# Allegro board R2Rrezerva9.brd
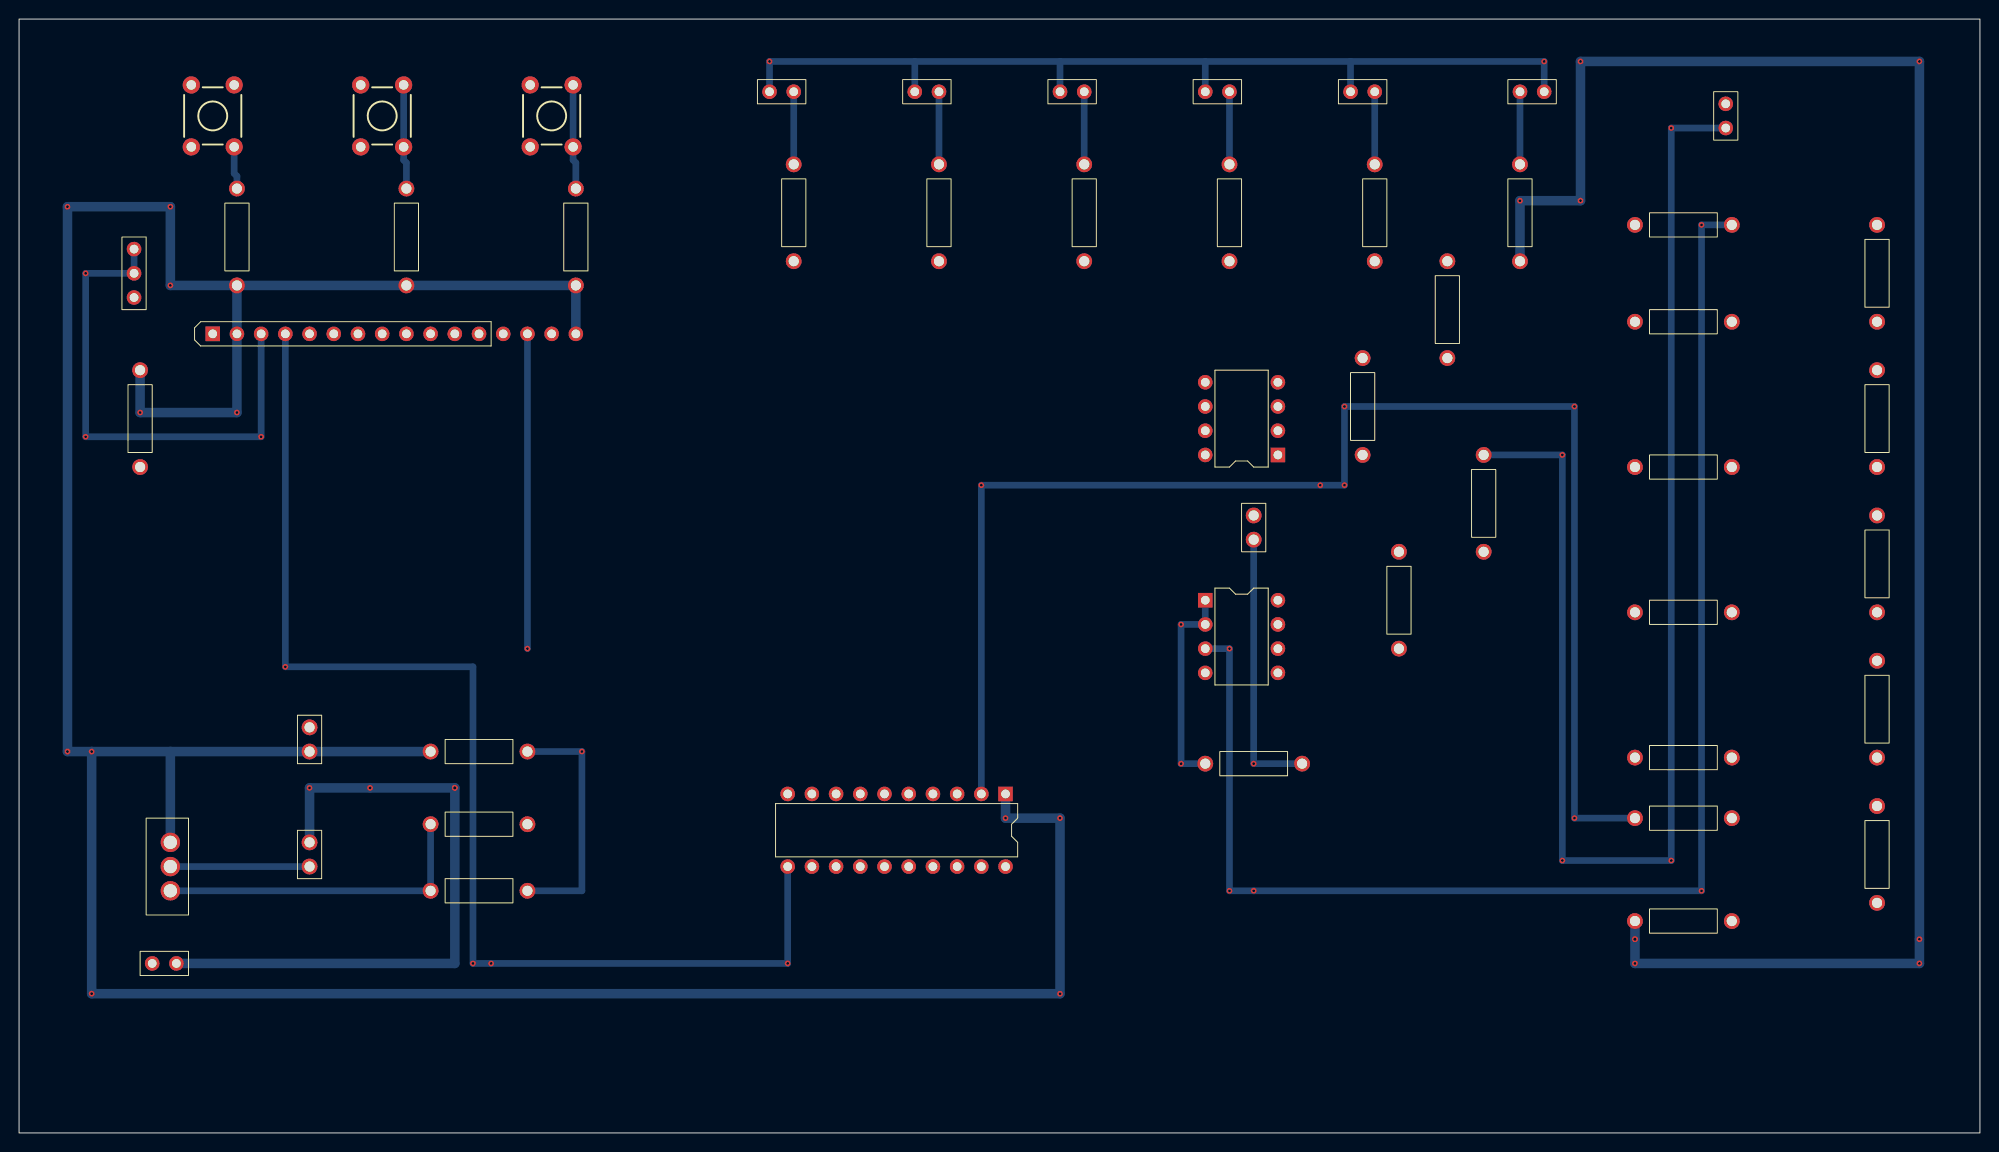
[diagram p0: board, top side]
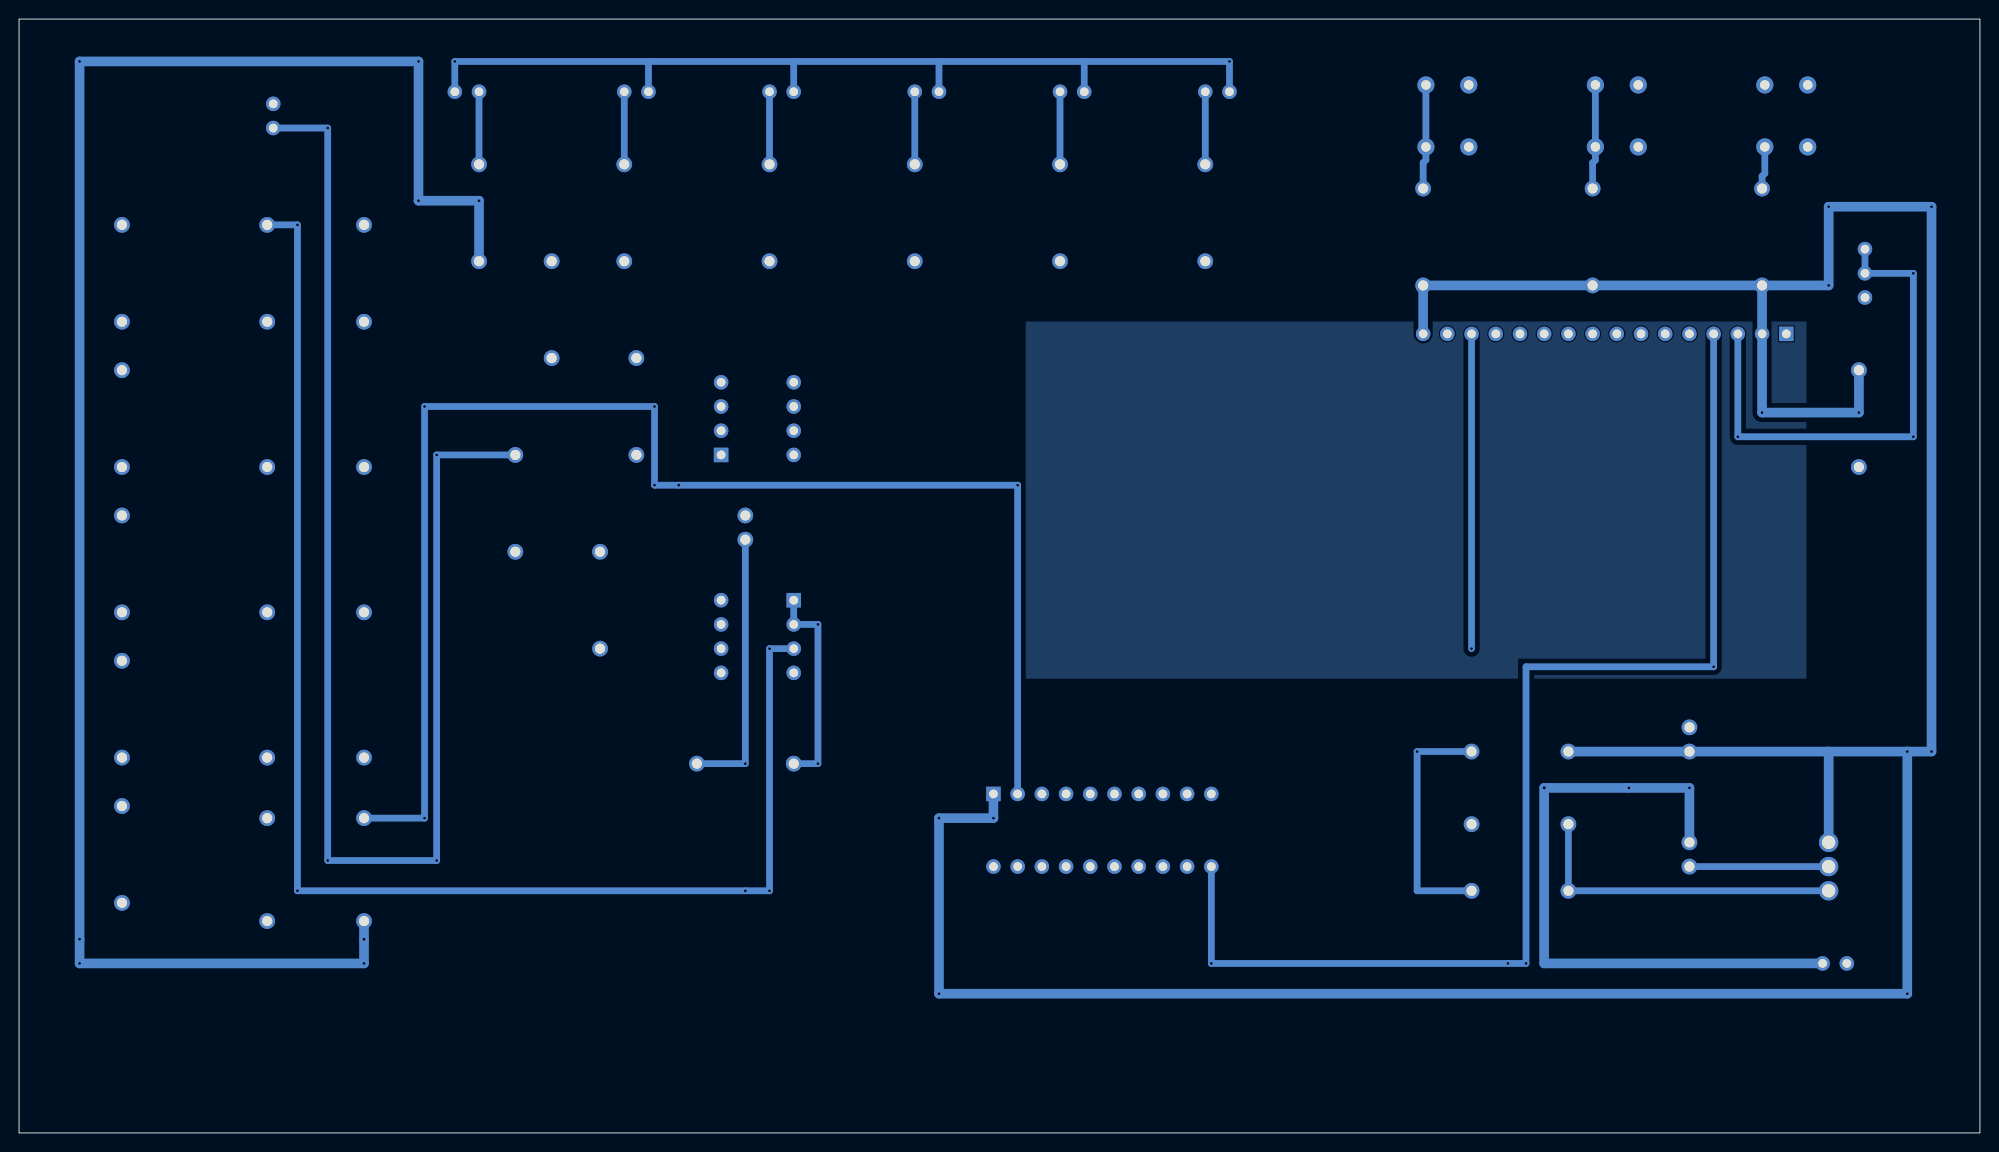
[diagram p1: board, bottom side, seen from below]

Outline 205.74 x 116.84 mm; copper layers: TOP, BOTTOM. Coordinates in mm from the lower left corner of the outline.
Outline path: rectangle 0,0 205.74,116.84

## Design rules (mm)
nets with their own width: min track width 0.7; nets N00328 N00332 N00336 N00340 N00355 N00470 N01662 N006340 N006500 N006660 N006820 N006980 N007140 N20855 N23488 N23661 N24189 N24193 N25824 N25853 N28143 N35057 N35516 N35592 N35638 N35656 N35674 N35692 N35721 N209781 SW1 SW2 SW3
nets with their own width: min track width 1; nets 0 9V V+ V- VCC

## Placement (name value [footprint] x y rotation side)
C3  10nf  [CAPCK05]  129.54 62.23 0 top
C4  10u  [CAPCK05]  30.48 30.48 180 top
C5  10u  [CAPCK05]  30.48 42.54 180 top
D1  MLED81  [JUMPER2]  78.74 109.22 0 top
D2  MLED81  [JUMPER2]  93.98 109.22 0 top
D3  MLED81  [JUMPER2]  109.22 109.22 0 top
D4  MLED81  [JUMPER2]  124.46 109.22 0 top
D5  MLED81  [JUMPER2]  139.7 109.22 0 top
D6  MLED81  [JUMPER2]  160.02 109.22 180 top
J1  Speaker  [JUMPER2]  179.07 105.41 90 top
J2  LCD 1602  [SIP16]  20.32 83.82 90 top
J3  ALIMENTARE 9V  [JUMPER2]  13.97 17.78 0 top
R2  1k  [RES400]  194.94 85.09 0 top
R3  1k  [RES400]  194.94 69.85 0 top
R4  1k  [RES400]  194.94 54.61 0 top
R5  1k  [RES400]  194.94 39.37 0 top
R6  1k  [RES400]  194.94 24.13 0 top
R7  2k  [RES400]  169.55 33.02 270 top
R8  2k  [RES400]  169.55 39.37 270 top
R9  2k  [RES400]  169.55 54.61 270 top
R10  2k  [RES400]  169.55 69.85 270 top
R11  2k  [RES400]  169.55 85.09 270 top
R12  2k  [RES400]  169.55 95.25 270 top
R13  2k  [RES400]  169.55 22.22 270 top
R14  470  [RES400]  157.48 91.44 0 top
R15  470  [RES400]  142.24 91.44 0 top
R16  470  [RES400]  127 91.44 0 top
R17  470  [RES400]  111.76 91.44 0 top
R18  470  [RES400]  96.52 91.44 0 top
R19  470  [RES400]  81.28 91.44 0 top
R20  10k  [RES400]  149.86 81.28 0 top
R22  10k  [RES400]  153.67 60.96 0 top
R23  1k  [RES400]  53.34 32.38 90 top
R24  470  [RES400]  53.34 40 90 top
R25  150  [RES400]  43.18 25.4 270 top
R26  33k  [RES400]  124.46 38.73 270 top
R27  10k  [RES400]  140.97 71.12 0 top
R28  10k  [RES400]  144.78 50.8 0 top
R29  1k  [JUMPER3]  12.06 87.63 90 top
R30  10k  [RES400]  22.86 99.06 180 top
R33  1k  [RES400]  12.7 80.01 180 top
R34  10k  [RES400]  40.64 99.06 180 top
R35  10k  [RES400]  58.42 99.06 180 top
SW7  SW_TC_SPST  [SW_SCHURTER_13019301L]  20.32 106.68 180 top
SW8  SW_TC_SPST  [SW_SCHURTER_13019301L]  38.1 106.68 180 top
SW9  SW_TC_SPST  [SW_SCHURTER_13019301L]  55.88 106.68 180 top
U1  MSP430G2553  [DIP20]  103.5 35.56 270 top
U7  LM317K  [TO220AB]  15.88 25.4 270 top
U9  LM358  [DIP8_3]  132.08 71.12 180 top
U10  LM358  [DIP8_3]  124.46 55.88 0 top

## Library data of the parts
C3-C5 = C: Tolerance: ***; User Part Number: ***
D1-D6 = MLED81: User Part Number: ***
J1 J3 = CON2: User Part Number: ***
J2 = CON16: User Part Number: ***
R2-R20 R22-R28 R30 R33-R35 = R: Tolerance: ***; User Part Number: ***
R29 = POT: User Part Number: ***
SW7-SW9 = SW_TC_SPST
U1 = MSP430G2553_4: Tolerance: ***; User Part Number: ***
U7 = LM317T
U9 = LM358: Tolerance: ***; User Part Number: ***
U10 = LM358_0: Tolerance: ***; User Part Number: ***

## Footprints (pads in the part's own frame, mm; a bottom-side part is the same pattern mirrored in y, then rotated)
CAPCK05
  round 1.651 hole 1.067: 1(0,0) 2(0,2.54)
DIP8_3
  rect 1.524x1.524 hole 0.914: 1(0,0)
  round 1.524 hole 0.914: 2(0,-2.54) 3(0,-5.08) 4(0,-7.62) 5(7.62,-7.62) 6(7.62,-5.08) 7(7.62,-2.54) 8(7.62,0)
DIP20
  rect 1.524x1.524 hole 0.914: 1(0,0)
  round 1.524 hole 0.914: 2(0,-2.54) 3(0,-5.08) 4(0,-7.62) 5(0,-10.16) 6(0,-12.7) 7(0,-15.24) 8(0,-17.78) 9(0,-20.32) 10(0,-22.86) 11(7.62,-22.86) 12(7.62,-20.32) 13(7.62,-17.78) 14(7.62,-15.24) 15(7.62,-12.7) 16(7.62,-10.16) 17(7.62,-7.62) 18(7.62,-5.08) 19(7.62,-2.54) 20(7.62,0)
JUMPER2
  round 1.524 hole 0.914: 1(0,0) 2(2.54,0)
JUMPER3
  round 1.524 hole 0.914: 1(0,0) 2(2.54,0) 3(5.08,0)
RES400
  round 1.651 hole 1.067: 1(0,0) 2(0,10.16)
SIP16
  rect 1.524x1.524 hole 0.914: 1(0,0)
  round 1.524 hole 0.914: 2(0,-2.54) 3(0,-5.08) 4(0,-7.62) 5(0,-10.16) 6(0,-12.7) 7(0,-15.24) 8(0,-17.78) 9(0,-20.32) 10(0,-22.86) 11(0,-25.4) 12(0,-27.94) 13(0,-30.48) 14(0,-33.02) 15(0,-35.56) 16(0,-38.1)
SW_SCHURTER_13019301L
  round 1.8 hole 1: 1(-2.25,-3.25) 2(-2.25,3.25) 3(2.25,3.25) 4(2.25,-3.25)
TO220AB
  round 2.032 hole 1.397: 1(0,0) 2(-2.54,0) 3(-5.08,0)

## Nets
9V: C4.1 J3.2 U9.8(V+)
VCC: C5.2 J2.2 J2.16 R24.2 R30.2 R33.1 R34.2 R35.2 U1.1(DVCC) U7.3(OUT)
0: C3.2 C5.1 J2.1 J2.5 J3.1 R13.1 R14.1 R15.1 R16.1 R17.1 R18.1 R19.1 R20.2 R23.1 R29.1 SW7.3 SW8.3 SW9.3 U1.20(GROUND) U9.4(V-) U9.5(+)
SW1: R30.1 SW7.1 SW7.2 U1.8(P2_0/CS(B0))
SW2: R34.1 SW8.1 SW8.2 U1.9(P2_1)
SW3: R35.1 SW9.1 SW9.2 U1.10(P2_2)
V+: U10.8(V+)
V-: U10.4(V-)
N00328: R2.1 R3.2 R11.2
N00332: R3.1 R4.2 R10.2
N00336: R4.1 R5.2 R9.2
N00340: R5.1 R6.2 R8.2
N00355: R2.2 R12.2 U10.3(+)
N00470: R6.1 R7.2 R13.2
N01662: D1.1(A) D2.1(A) D3.1(A) D4.1(A) D5.1(A) D6.1(A) R7.1 R8.1 R9.1 R10.1 R11.1 R12.1 U1.2(P1_0/A0/RED_LED) U1.3(P1_1/A1/RXD) U1.4(P1_2/A2/TXD) U1.5(P1_3/A3/PUSH2) U1.6(P1_4/A4) U1.7(P1_5/A5/SCK(B0))
N006340: D6.2(C) R14.2
N006500: D5.2(C) R15.2
N006660: D4.2(C) R16.2
N006820: D3.2(C) R17.2
N006980: D2.2(C) R18.2
N007140: D1.2(C) R19.2
N20855: R23.2 R25.1 U7.1(ADJ)
N23488: C3.1 R26.2 U9.3(+)
N23661: R26.1 U10.1(OUT) U10.2(-)
N24189: R20.1 R27.2 U9.2(-)
N24193: J1.1 R22.2 R27.1 U9.1(OUT)
N25824: R22.1 R28.2 U9.6(-)
N25853: J1.2 R28.1 U9.7(OUT)
N28143: C4.2 U7.2(IN)
N35057: J2.3 R29.2(T) R29.3(2)
N35516: J2.4 U1.11(P2_3)
N35592: J2.6 U1.12(P2_4)
N35638: J2.11 U1.13(P2_5)
N35656: J2.12 U1.14(P1_6/A6/SCL/MISO(B0)/GREEN LED)
N35674: J2.13 U1.15(P1_7/A7/SDA/MOSE(B0))
N35692: J2.14 U1.18(P2_7/XOUT)
N35721: J2.15 R33.2
N209781: R24.1 R25.2

Pads without a net: J2 7 8 9 10; SW7 4; SW8 4; SW9 4; U1 16 17 19; U10 5 6 7

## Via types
v1: diameter 0.6, hole 0.3, TOP to BOTTOM, 54 vias

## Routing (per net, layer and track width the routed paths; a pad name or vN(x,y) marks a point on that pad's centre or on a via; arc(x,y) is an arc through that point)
9V: length 68.6
  BOTTOM w1: C4.1 v1(30.48,36.19) v1(36.83,36.19) v1(45.72,36.19) 45.72,17.78 J3.2
VCC: length 353.1
  BOTTOM w1: J2.16 R35.2 R34.2 R30.2 ; R30.2 J2.2 v1(22.86,75.56) v1(12.7,75.56) R33.1 ; R30.2 v1(15.88,88.9) v1(15.88,97.15) v1(5.08,97.15) v1(5.08,40) v1(7.62,40) ; U1.1 v1(103.5,33.02) v1(109.22,33.02) v1(109.22,14.6) v1(7.62,14.6) v1(7.62,40) ; 15.88,40 U7.3 ; 15.88,40 v1(7.62,40) ; 15.88,40 C5.2 R24.2
0: length 191.8
  BOTTOM w1: R14.1 v1(157.48,97.79) v1(163.83,97.79) v1(163.83,112.39) v1(199.39,112.39) v1(199.39,20.32) v1(199.39,17.78) v1(169.55,17.78) v1(169.55,20.32) R13.1
SW1: length 4.5
  BOTTOM w0.7: SW7.2 22.57,100.65 22.86,100.36 R30.1
SW2: length 11
  BOTTOM w0.7: SW8.1 SW8.2 40.35,102.05 40.64,101.76 R34.1
SW3: length 11
  BOTTOM w0.7: R35.1 58.42,101.76 58.13,102.05 SW9.2 SW9.1
N00355: length 150.5
  BOTTOM w0.7: R12.2 v1(176.53,95.25) v1(176.53,25.4) v1(129.54,25.4) v1(127,25.4) v1(127,50.8) U10.3
N01662: length 252.7
  BOTTOM w0.7: 139.7,112.39 v1(160.02,112.39) D6.1 ; 139.7,112.39 124.46,112.39 ; 139.7,112.39 D5.1 ; 124.46,112.39 D4.1 ; 124.46,112.39 109.22,112.39 ; 93.98,112.39 D2.1 ; 93.98,112.39 v1(78.74,112.39) D1.1 ; 93.98,112.39 109.22,112.39 ; U1.2 v1(100.97,67.94) v1(136.53,67.94) v1(139.06,67.94) v1(139.06,76.2) v1(163.19,76.2) v1(163.19,33.02) R7.1 ; 109.22,112.39 D3.1
N006340: length 7.6
  BOTTOM w0.7: R14.2 D6.2
N006500: length 7.6
  BOTTOM w0.7: R15.2 D5.2
N006660: length 7.6
  BOTTOM w0.7: R16.2 D4.2
N006820: length 7.6
  BOTTOM w0.7: R17.2 D3.2
N006980: length 7.6
  BOTTOM w0.7: R18.2 D2.2
N007140: length 7.6
  BOTTOM w0.7: R19.2 D1.2
N20855: length 34.3
  BOTTOM w0.7: U7.1 R25.1 R23.2
N23488: length 28.6
  BOTTOM w0.7: R26.2 v1(129.54,38.73) v1(129.54,62.23)
N23661: length 22.2
  BOTTOM w0.7: U10.1 U10.2 v1(121.92,53.34) v1(121.92,38.73) R26.1
N24193: length 144.8
  BOTTOM w0.7: R22.2 v1(161.93,71.12) v1(161.93,28.57) v1(173.36,28.57) v1(173.36,105.41) J1.1
N28143: length 14.6
  BOTTOM w0.7: U7.2 C4.2
N35057: length 54
  BOTTOM w0.7: J2.3 v1(25.4,73.02) v1(6.99,73.02) v1(6.99,90.17) R29.2 R29.3
N35516: length 128.9
  BOTTOM w0.7: J2.4 v1(27.94,48.89) 47.62,48.89 v1(47.62,17.78) v1(49.53,17.78) v1(80.65,17.78) U1.11
N35692: length 33
  BOTTOM w0.7: v1(53.34,50.8) J2.14
N209781: length 26
  BOTTOM w0.7: R24.1 v1(59.06,40) 59.06,25.4 R25.2

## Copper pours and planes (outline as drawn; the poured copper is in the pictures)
Net_1 on BOTTOM: 18.21,85.12 18.21,47.65 100.13,47.65 100.13,85.12
